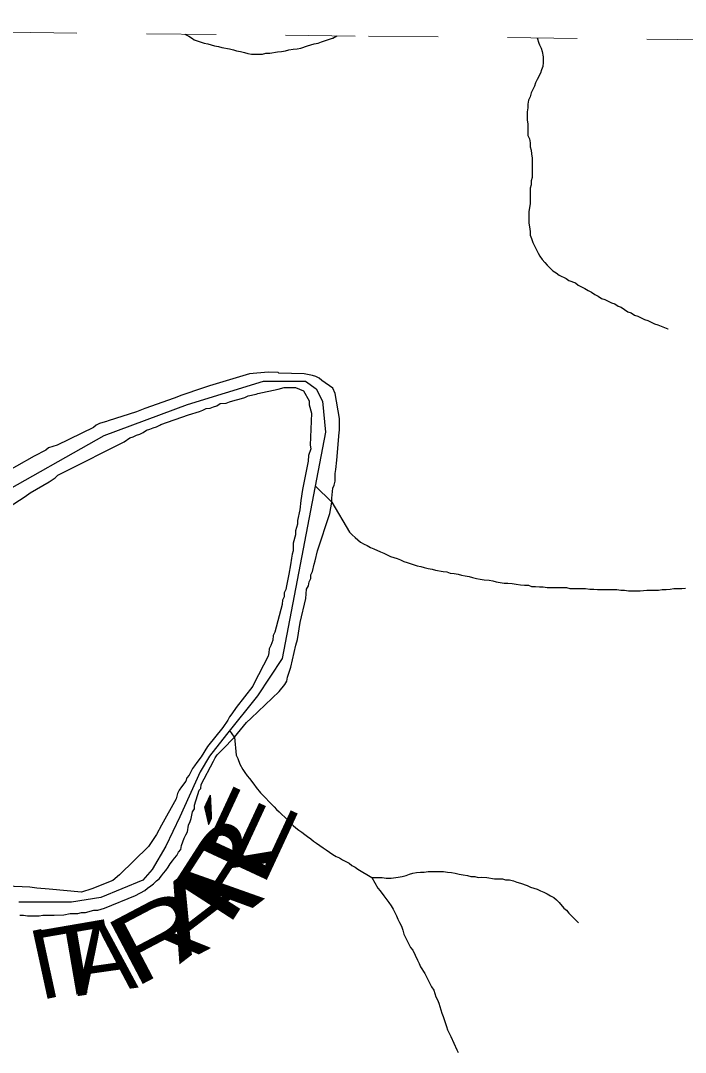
# Model space of a CAD drawing. Extents: x 652.3 to 678, y 7316.9 to 7344.9.
# Drawn here: x 654.161 to 655.117, y 7343.443 to 7344.926 of the extents above; entities that cross this region are included whole.
import ezdxf
from ezdxf.enums import TextEntityAlignment as Align

# ---------------------------------------------------------------- set-up
doc = ezdxf.new("R2010")
doc.units = 0
doc.header["$LTSCALE"] = 0.032
doc.linetypes.add('SHORT_DASHED', pattern=[2.7, 1.5, -1.2])
for name, color, linetype, lineweight in [('2', 7, 'Continuous', 25), ('53', 7, 'SHORT_DASHED', 13), ('55', 7, 'Continuous', 25), ('7', 7, 'Continuous', 25)]:
    doc.layers.add(name, color=color, linetype=linetype, lineweight=lineweight)
doc.layers.add('61', color=7, linetype='Continuous')

msp = doc.modelspace()

# ---------------------------------------------------------------- linework, layer by layer
at = {"layer": '2'}
msp.add_line((654.4517, 7343.9099), (654.4294, 7343.8829), dxfattribs=at)
for points in [[(654.532, 7344.4192), (654.5312, 7344.42), (654.5169, 7344.4208), (654.4898, 7344.4184), (654.4326, 7344.4009), (654.4222, 7344.3977), (654.3928, 7344.3873), (654.3816, 7344.3834), (654.3395, 7344.3682), (654.3275, 7344.3635), (654.2869, 7344.3507), (654.2846, 7344.3499), (654.279, 7344.3484), (654.2742, 7344.3468), (654.2694, 7344.3444), (654.2655, 7344.3412), (654.2137, 7344.3157), (654.201, 7344.3118), (654.197, 7344.3086), (654.1803, 7344.2998), (654.1294, 7344.2712)], [(654.6084, 7344.2339), (654.6084, 7344.2393), (654.61, 7344.2537), (654.6116, 7344.2584), (654.6132, 7344.264), (654.6132, 7344.2696), (654.6132, 7344.2752), (654.614, 7344.2807), (654.6156, 7344.2943), (654.6187, 7344.334), (654.6195, 7344.3372), (654.6195, 7344.3428), (654.6195, 7344.3484), (654.6195, 7344.3539), (654.6132, 7344.3897), (654.61, 7344.3977), (654.5941, 7344.4088), (654.5901, 7344.412), (654.5853, 7344.4144), (654.5806, 7344.416), (654.5686, 7344.4184), (654.532, 7344.4192)], [(654.135, 7344.221), (654.1676, 7344.2417), (654.1748, 7344.2473), (654.2018, 7344.2632), (654.2106, 7344.2688), (654.2145, 7344.2728), (654.2193, 7344.2752), (654.2241, 7344.2775), (654.31, 7344.3205), (654.318, 7344.3261), (654.3227, 7344.3277), (654.3275, 7344.3301), (654.3323, 7344.3316), (654.3371, 7344.334), (654.3418, 7344.3372), (654.3466, 7344.3388), (654.3514, 7344.3404), (654.3562, 7344.342), (654.3609, 7344.3444), (654.3625, 7344.3452), (654.4023, 7344.3595), (654.4182, 7344.3643), (654.423, 7344.3659), (654.4278, 7344.3682), (654.4333, 7344.369), (654.4381, 7344.3706), (654.4429, 7344.3722), (654.4477, 7344.3754), (654.4564, 7344.3762), (654.4612, 7344.3778), (654.466, 7344.3794), (654.4787, 7344.3826), (654.4835, 7344.3842), (654.4883, 7344.3866), (654.4994, 7344.3889), (654.5018, 7344.3897), (654.5312, 7344.3961), (654.54, 7344.3985), (654.5559, 7344.3985), (654.5678, 7344.3937), (654.5758, 7344.3794), (654.5758, 7344.3738), (654.579, 7344.3619), (654.5774, 7344.3157), (654.5782, 7344.3102), (654.575, 7344.3006), (654.5742, 7344.2927), (654.5662, 7344.2521), (654.5638, 7344.2362), (654.5623, 7344.2226), (654.5591, 7344.2075), (654.5591, 7344.202), (654.5575, 7344.1972), (654.5559, 7344.1924), (654.5559, 7344.1868), (654.5527, 7344.1749), (654.5527, 7344.1693), (654.5527, 7344.1638), (654.5511, 7344.159), (654.5503, 7344.1534), (654.5487, 7344.1439), (654.5463, 7344.1303), (654.5432, 7344.1136), (654.5424, 7344.1081), (654.54, 7344.1033), (654.54, 7344.0977), (654.5376, 7344.0929), (654.5368, 7344.0874), (654.5368, 7344.0866), (654.5264, 7344.0468), (654.5241, 7344.042), (654.5233, 7344.0357), (654.5209, 7344.0277), (654.5185, 7344.0229), (654.5177, 7344.0174), (654.5169, 7344.0126), (654.4962, 7343.9728), (654.4946, 7343.9696), (654.4707, 7343.9386), (654.4644, 7343.9298), (654.4612, 7343.9251), (654.4588, 7343.9203), (654.4517, 7343.9099)], [(654.6053, 7344.2173), (654.6084, 7344.2339), (654.6084, 7344.2339)], [(654.4859, 7343.9171), (654.4922, 7343.9235), (654.5328, 7343.9617), (654.5408, 7343.972), (654.5439, 7343.9768), (654.5447, 7343.9823), (654.5495, 7343.9967), (654.5567, 7344.0285), (654.5591, 7344.0364), (654.563, 7344.0611), (654.571, 7344.0953), (654.5718, 7344.1089), (654.575, 7344.1136), (654.5758, 7344.1192), (654.5782, 7344.124), (654.5782, 7344.1295), (654.5806, 7344.1343), (654.5829, 7344.1447), (654.5845, 7344.1494), (654.5877, 7344.1638), (654.6053, 7344.2173)], [(654.4686, 7343.896), (654.4686, 7343.896), (654.4859, 7343.9171)], [(654.4513, 7343.8782), (654.4686, 7343.896), (654.4686, 7343.896)], [(654.1596, 7343.6402), (654.1652, 7343.6402), (654.1708, 7343.6394), (654.1763, 7343.6394), (654.1819, 7343.6394), (654.1875, 7343.6394), (654.1931, 7343.6402), (654.209, 7343.6402), (654.2233, 7343.641), (654.232, 7343.6426), (654.2376, 7343.6426), (654.2432, 7343.6426), (654.2487, 7343.6442), (654.2543, 7343.6442), (654.2663, 7343.6474), (654.2718, 7343.6474), (654.2814, 7343.6505), (654.3259, 7343.6688), (654.3395, 7343.676), (654.3434, 7343.6792), (654.3482, 7343.6824), (654.3522, 7343.6855), (654.3562, 7343.6895), (654.3601, 7343.6927), (654.3633, 7343.6967), (654.3665, 7343.7007), (654.3697, 7343.7046), (654.3729, 7343.7094), (654.3761, 7343.7142), (654.3792, 7343.7182), (654.3824, 7343.7222), (654.3856, 7343.7261), (654.388, 7343.7309), (654.3912, 7343.7349), (654.392, 7343.7405), (654.396, 7343.7508), (654.3983, 7343.7556), (654.4007, 7343.7603), (654.4023, 7343.7699), (654.4047, 7343.7747), (654.4063, 7343.7794), (654.4079, 7343.789), (654.4111, 7343.793), (654.4111, 7343.7985), (654.4174, 7343.82), (654.4198, 7343.8224), (654.4206, 7343.828), (654.4381, 7343.8614), (654.4405, 7343.8662), (654.4437, 7343.8709), (654.4513, 7343.8782)], [(654.4294, 7343.8829), (654.4206, 7343.8678), (654.4143, 7343.8598), (654.4111, 7343.855), (654.4079, 7343.8511), (654.4031, 7343.8415), (654.3999, 7343.8375), (654.3983, 7343.8328), (654.392, 7343.8248), (654.3888, 7343.82), (654.3864, 7343.8152), (654.3848, 7343.8073)], [(654.3848, 7343.8073), (654.3633, 7343.7699), (654.3562, 7343.7564), (654.345, 7343.7389), (654.3029, 7343.6983), (654.2933, 7343.6903), (654.2631, 7343.6784), (654.2487, 7343.6736), (654.2018, 7343.6776), (654.1843, 7343.6792), (654.174, 7343.6808), (654.0952, 7343.684), (654.0737, 7343.684), (654.0737, 7343.684), (654.0554, 7343.684), (654.0554, 7343.684)]]:
    msp.add_lwpolyline(points, dxfattribs=at)
at = {"layer": '53'}
msp.add_lwpolyline([(652.5847, 7344.9257), (653.1037, 7344.9201), (653.6228, 7344.9146), (654.1419, 7344.909), (654.661, 7344.9034), (655.1801, 7344.8978), (655.6991, 7344.8922), (656.2182, 7344.8865), (656.7373, 7344.8808), (657.2564, 7344.8752), (657.7755, 7344.8694), (658.2945, 7344.8637), (658.8136, 7344.858), (659.3327, 7344.8522)], dxfattribs=at)
at = {"layer": '55'}
for p, q in [((654.5845, 7344.2574), (654.6084, 7344.2339)), ((654.4686, 7343.896), (654.4615, 7343.9058))]:
    msp.add_line(p, q, dxfattribs=at)
msp.add_lwpolyline([(654.1228, 7344.2406), (654.2809, 7344.3297), (654.4011, 7344.3743), (654.5102, 7344.4077), (654.5703, 7344.4077), (654.5859, 7344.3966), (654.5948, 7344.3788), (654.5992, 7344.3342), (654.5369, 7344.009), (654.5013, 7343.9555), (654.4567, 7343.8998), (654.4323, 7343.8686), (654.4189, 7343.8463), (654.39, 7343.7817), (654.3699, 7343.7394), (654.3499, 7343.706), (654.3365, 7343.6904), (654.2764, 7343.6659), (654.2341, 7343.6592), (654.1584, 7343.6592)], dxfattribs=at)
at = {"layer": '7'}
msp.add_line((654.397, 7344.9062), (654.4019, 7344.9037), dxfattribs=at)
for points in [[(654.4019, 7344.9037), (654.4026, 7344.9033), (654.4079, 7344.8998), (654.4103, 7344.8982), (654.4246, 7344.8934), (654.4302, 7344.8926), (654.4349, 7344.891), (654.4397, 7344.8894), (654.4453, 7344.8886), (654.4501, 7344.887), (654.4612, 7344.8854), (654.4668, 7344.8839), (654.4715, 7344.8823), (654.4771, 7344.8815), (654.4827, 7344.8799), (654.4875, 7344.8783), (654.493, 7344.8775), (654.501, 7344.8775), (654.5089, 7344.8775), (654.5137, 7344.8791), (654.5193, 7344.8791), (654.5304, 7344.8807), (654.536, 7344.8815), (654.5416, 7344.8823), (654.5463, 7344.8839), (654.5527, 7344.8847), (654.5583, 7344.8854), (654.5638, 7344.8862), (654.5734, 7344.8894), (654.5782, 7344.891), (654.5829, 7344.8926), (654.5885, 7344.8934), (654.5933, 7344.895), (654.6092, 7344.9006), (654.6096, 7344.9007), (654.6154, 7344.9039)], [(654.9035, 7344.9008), (654.906, 7344.8934), (654.9068, 7344.891), (654.9092, 7344.8862), (654.9108, 7344.8815), (654.9124, 7344.8735), (654.9124, 7344.8656), (654.9116, 7344.86), (654.91, 7344.8552), (654.9084, 7344.8504), (654.9036, 7344.8409), (654.9012, 7344.8361), (654.8996, 7344.8313), (654.8948, 7344.8218), (654.8933, 7344.8162), (654.8909, 7344.8114), (654.8901, 7344.8059), (654.8901, 7344.8003), (654.8893, 7344.7947), (654.8893, 7344.7828), (654.8901, 7344.7772), (654.8901, 7344.7605), (654.8925, 7344.7557), (654.8933, 7344.7502), (654.8933, 7344.7446), (654.8948, 7344.7398), (654.8956, 7344.7343), (654.8964, 7344.7279), (654.8964, 7344.7001), (654.8948, 7344.6953), (654.8948, 7344.6897), (654.8933, 7344.6849), (654.8933, 7344.6627), (654.8917, 7344.6515), (654.8917, 7344.6348), (654.8925, 7344.6292), (654.8933, 7344.6229), (654.8933, 7344.6173), (654.8956, 7344.6125), (654.8972, 7344.607), (654.8996, 7344.6022), (654.9028, 7344.5966), (654.9052, 7344.5918), (654.9076, 7344.5871), (654.9108, 7344.5823), (654.9147, 7344.5783), (654.9179, 7344.5743), (654.9259, 7344.5664), (654.9307, 7344.5632), (654.9354, 7344.56), (654.945, 7344.5552), (654.949, 7344.5521), (654.9585, 7344.5489), (654.9625, 7344.5457), (654.9673, 7344.5433), (654.972, 7344.5409), (654.9768, 7344.5377), (654.9816, 7344.5353), (654.9864, 7344.5322), (654.9911, 7344.5298), (654.9959, 7344.5266), (655.0007, 7344.525), (655.0102, 7344.5202), (655.015, 7344.5186), (655.0198, 7344.5155), (655.0245, 7344.5139), (655.0293, 7344.5107), (655.0341, 7344.5075), (655.0389, 7344.5059), (655.0436, 7344.5027), (655.0484, 7344.5011), (655.0532, 7344.4987), (655.058, 7344.4964), (655.0627, 7344.4948), (655.0675, 7344.4924), (655.0723, 7344.49), (655.0771, 7344.4884), (655.0914, 7344.4828), (655.0918, 7344.4827)], [(654.6084, 7344.2339), (654.6339, 7344.1908), (654.6378, 7344.1868), (654.6418, 7344.1829), (654.6458, 7344.1797), (654.6498, 7344.1765), (654.6546, 7344.1733), (654.6593, 7344.1717), (654.6641, 7344.1685), (654.6689, 7344.1669), (654.6784, 7344.1622), (654.6832, 7344.1606), (654.6927, 7344.1558), (654.7023, 7344.1526), (654.7071, 7344.151), (654.7118, 7344.1486), (654.7166, 7344.147), (654.7309, 7344.1423), (654.7365, 7344.1415), (654.7413, 7344.1399), (654.7469, 7344.1383), (654.7524, 7344.1375), (654.7572, 7344.1359), (654.7683, 7344.1343), (654.7739, 7344.1335), (654.7787, 7344.1319), (654.7842, 7344.1311), (654.7898, 7344.1303), (654.7946, 7344.1287), (654.8002, 7344.128), (654.8057, 7344.1272), (654.8105, 7344.1256), (654.8161, 7344.124), (654.8216, 7344.1232), (654.8272, 7344.1224), (654.8344, 7344.1216), (654.8399, 7344.1208), (654.8447, 7344.1192), (654.8503, 7344.1184), (654.8559, 7344.1176), (654.8614, 7344.1176), (654.8678, 7344.1168), (654.8734, 7344.116), (654.8797, 7344.1152), (654.8853, 7344.1144), (654.8909, 7344.1144), (654.8956, 7344.1128), (654.9012, 7344.1128), (654.9068, 7344.112), (654.9124, 7344.112), (654.9179, 7344.1112), (654.9458, 7344.1112), (654.9505, 7344.1097), (654.9728, 7344.1097), (654.9792, 7344.1089), (654.9848, 7344.1089), (654.9903, 7344.1081), (655.0182, 7344.1081), (655.0237, 7344.1073), (655.0293, 7344.1073), (655.0349, 7344.1065), (655.0516, 7344.1065), (655.0611, 7344.1073), (655.0779, 7344.1073), (655.0834, 7344.1081), (655.089, 7344.1081), (655.0946, 7344.1089), (655.1001, 7344.1097), (655.1113, 7344.1097), (655.1168, 7344.1104)], [(654.4686, 7343.896), (654.4707, 7343.8701), (654.4731, 7343.8654), (654.4763, 7343.8574), (654.4803, 7343.8495), (654.4835, 7343.8455), (654.4867, 7343.8407), (654.4898, 7343.8367), (654.4962, 7343.8288), (654.4994, 7343.824), (654.5058, 7343.816), (654.5256, 7343.7961), (654.5288, 7343.7922), (654.5328, 7343.789), (654.5447, 7343.7771), (654.5487, 7343.7731), (654.5527, 7343.7691), (654.5567, 7343.7659), (654.5607, 7343.7627), (654.5654, 7343.7595), (654.5694, 7343.7564), (654.5734, 7343.7532), (654.5782, 7343.75), (654.5821, 7343.7468), (654.5861, 7343.7436), (654.5909, 7343.7405), (654.5957, 7343.7373), (654.6004, 7343.7341), (654.6052, 7343.7309), (654.61, 7343.7277), (654.6148, 7343.7245), (654.6195, 7343.7229), (654.6235, 7343.7198), (654.6331, 7343.715), (654.637, 7343.7118), (654.6418, 7343.7094), (654.6458, 7343.7062), (654.6657, 7343.6943)], [(654.6657, 7343.6943), (654.6808, 7343.6943), (654.6864, 7343.6935), (654.6935, 7343.6935), (654.7039, 7343.6951), (654.7095, 7343.6959), (654.715, 7343.6975), (654.7198, 7343.6991), (654.7246, 7343.7007), (654.7301, 7343.7015), (654.7357, 7343.7023), (654.7413, 7343.7023), (654.7469, 7343.7031), (654.7691, 7343.7031), (654.7747, 7343.7023), (654.7803, 7343.7015), (654.7858, 7343.7007), (654.7914, 7343.6991), (654.797, 7343.6983), (654.8033, 7343.6975), (654.8081, 7343.6959), (654.8137, 7343.6959), (654.8185, 7343.6943), (654.824, 7343.6951), (654.8312, 7343.6943), (654.8423, 7343.6927), (654.8535, 7343.6927), (654.8582, 7343.6911), (654.8638, 7343.6911), (654.8694, 7343.6895), (654.8742, 7343.6879), (654.8797, 7343.6863), (654.8893, 7343.6832), (654.8941, 7343.6808), (654.8988, 7343.6792), (654.9036, 7343.6776), (654.9084, 7343.6752), (654.9131, 7343.6736), (654.9179, 7343.6712), (654.9227, 7343.668), (654.9275, 7343.6657), (654.9315, 7343.6625), (654.9354, 7343.6585), (654.9418, 7343.6505), (654.9458, 7343.6474), (654.949, 7343.6434), (654.9561, 7343.6362), (654.9629, 7343.6295), (654.9631, 7343.6292)], [(654.6657, 7343.6943), (654.6744, 7343.6792), (654.6776, 7343.6752), (654.6832, 7343.668), (654.6904, 7343.6585), (654.6935, 7343.6537), (654.6967, 7343.6489), (654.7015, 7343.6394), (654.7031, 7343.6346), (654.7055, 7343.6299), (654.7087, 7343.6243), (654.7102, 7343.6187), (654.7118, 7343.6131), (654.7166, 7343.6036), (654.719, 7343.5988), (654.7214, 7343.594), (654.7246, 7343.5901), (654.7317, 7343.5757), (654.7341, 7343.571), (654.7357, 7343.5662), (654.7421, 7343.5566), (654.7445, 7343.5519), (654.7516, 7343.5376), (654.7548, 7343.5328), (654.758, 7343.5232), (654.7604, 7343.5185), (654.762, 7343.5137), (654.7667, 7343.4994), (654.7683, 7343.4946), (654.7731, 7343.4803), (654.7747, 7343.4755), (654.7795, 7343.4659), (654.7882, 7343.4468), (654.7896, 7343.4439), (654.7899, 7343.4432)]]:
    msp.add_lwpolyline(points, dxfattribs=at)

# ---------------------------------------------------------------- texts
at = {"layer": '61'}
for s, rotation, width, p in [('É', 65.07, 1.45, (654.5355, 7343.7353)), ('R', 57.227, 1.5, (654.4969, 7343.6808)), ('A', 37.563, 1.75, (654.4508, 7343.6169)), ('R', 27.732, 1.4, (654.3827, 7343.5658)), ('T', 9.753, 1.3, (654.2493, 7343.5275))]:
    msp.add_text(s, height=0.1, rotation=rotation, dxfattribs=dict(at, width=width)).set_placement(p, align=Align.CENTER)
for s, rotation, p in [('A', 8.068, (654.2867, 7343.5302)), ('I', 12.276, (654.2058, 7343.5215))]:
    msp.add_text(s, height=0.1, rotation=rotation, dxfattribs=at).set_placement(p, align=Align.CENTER)

doc.saveas('drawing.dxf')
